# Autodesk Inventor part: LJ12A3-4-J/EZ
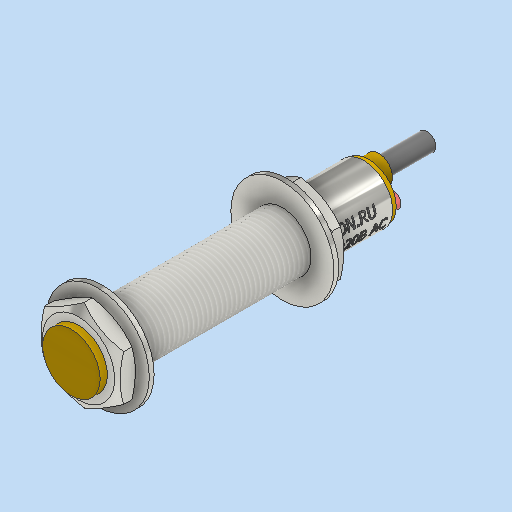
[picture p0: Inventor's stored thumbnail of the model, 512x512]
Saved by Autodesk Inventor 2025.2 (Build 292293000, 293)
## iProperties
Created: 2026-04
Part Number: LJ12A3-4-J/EZ
Material: Типовые
Description: D290-00326
Document SubType Name: Modeling
Designer: DN.RU
Mass: 50 g
Surface Area: 41.1946 cm^2
Volume: 8.64673 cm^3
Density: 5.78253 g/cm^3
Appearance: По умолчанию
Title: Концевой выключатель DN.ru
Author: DN.RU
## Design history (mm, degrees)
sketch "Эскиз1"
  geometry: C1 r 6 at (0, 0); 1 further point
  constraints: 1 centre point, 1 coincident
  dimensions: "d0" = 12 diameter of C1
extrude "Выдавливание1" new body sketch "Эскиз1" distance "d1" = 0.5; taper "d2" = 0 deg
sketch "Эскиз2"
  geometry: C1 r 6 at (0, 0); 1 further point
  constraints: 1 centre point, 1 coincident
  dimensions: "d3" = 12 diameter of C1
extrude "Выдавливание2" join sketch "Эскиз2" distance "d4" = 1; taper "d5" = 0 deg
sketch "Эскиз3"
  geometry: L1 (0, 0)-(8.25, 0); L2 (8.25, -4.763)-(0, -9.526); L3 (0, -9.526)-(-8.25, -4.763); L4 (-8.25, -4.763)-(-8.25, 4.763); L5 (-8.25, 4.763)-(0, 9.526); L6 (0, 9.526)-(8.25, 4.763); L7 (8.25, 4.763)-(8.25, -4.763); 1 further point
  constraints: 14 end point, 1 coincident, 1 horizontal, 1 midpoint, 13 other
  dimensions: "d6" = 8.25 distance of L1.start L1.end
extrude "Выдавливание3" join sketch "Эскиз3" distance "d7" = 4; taper "d8" = 0 deg
sketch "Эскиз4"
  geometry: C1 r 10.75 at (0, 0); 1 further point
  constraints: 1 centre point, 1 coincident
  dimensions: "d9" = 21.5 diameter of C1
extrude "Выдавливание4" join sketch "Эскиз4" distance "d10" = 1; taper "d11" = 0 deg
sketch "Эскиз5"
  geometry: C1 r 6 at (0, 0); 1 further point
  constraints: 1 centre point, 1 coincident
  dimensions: "d12" = 12 diameter of C1
extrude "Выдавливание5" join sketch "Эскиз5" distance "d13" = 37.5; taper "d14" = 0 deg
sketch "Эскиз6"
  geometry: C1 r 10.75 at (0, 0) reference; 1 further point
extrude "Выдавливание6" join sketch "Эскиз6" distance "d15" = 1; taper "d16" = 0 deg
sketch "Эскиз7"
  geometry: L1 (0, 9.526)-(-8.25, 4.763) reference; L2 (8.25, 4.763)-(0, 9.526) reference; L3 (8.25, -4.763)-(8.25, 4.763) reference; L4 (0, -9.526)-(8.25, -4.763) reference; L5 (-8.25, -4.763)-(0, -9.526) reference; L6 (-8.25, 4.763)-(-8.25, -4.763) reference; C1 r 6 at (0, 0) reference; 1 further point
extrude "Выдавливание7" join sketch "Эскиз7" distance "d17" = 4; taper "d18" = 0 deg
sketch "Эскиз9"
  geometry: C1 r 6 at (0, 0); 1 further point
  constraints: 1 centre point, 1 coincident
  dimensions: "d22" = 12 diameter of C1
extrude "Выдавливание9" join sketch "Эскиз9" distance "d23" = 12; taper "d24" = 0 deg
sketch "Эскиз10"
  geometry: C1 r 5.75 at (0, 0); 1 further point
  constraints: 1 centre point, 1 coincident
  dimensions: "d25" = 11.5 diameter of C1
extrude "Выдавливание10" join sketch "Эскиз10" distance "d26" = 1; taper "d27" = 0 deg
sketch "Эскиз11"
  geometry: C1 r 5.75 at (0, 0) reference; C2 r 1.559 at (-4.191, 0); 2 further points
  constraints: 1 centre point, 1 horizontal alignment, 3 other
extrude "Выдавливание11" join sketch "Эскиз11" distance "d29" = 1; taper "d30" = 0 deg
node "Непосредственное редактирование1"
sketch "Эскиз12"
  geometry: C1 r 2.875 at (0, 0) reference; C2 r 1.875 at (0, 0); 1 further point
  constraints: 1 centre point
  dimensions: "d34" = 1 radial gap between concentric circles of C1 C2
extrude "Выдавливание12" join sketch "Эскиз12" distance "d35" = 10; taper "d36" = 0 deg
feature "Резьба1" dims "d37" = 37.5, "d38" = 0
sketch "Эскиз13"
  geometry: L1 (6, 0.5)-(-6, 0.5) reference; L2 (0, 0.5)-(0, 6.956); L3 (9.526, -1)-(9.526, -5) reference; L4 (9.526, -3)-(12.26, -3); L5 (6, -6)-(6, -43.5) reference; L6 (6, -24.75)-(19.06, -24.75); L7 (9.526, -1)-(7.526, -1); L8 (4.763, -1)-(9.526, -1) reference; L9 (7.526, -1)-(9.897, -2.369); L10 (9.897, -2.369)-(9.897, -1); L11 (9.897, -1)-(9.526, -1); L12 (9.526, -5)-(7.526, -5); L13 (7.526, -5)-(9.897, -3.631); L14 (9.897, -3.631)-(9.897, -5); L15 (9.897, -5)-(9.526, -5); L16 (9.526, -48.5)-(7.526, -48.5); L17 (9.897, -48.5)-(9.526, -48.5); L18 (7.526, -48.5)-(9.897, -47.131); L19 (9.897, -47.131)-(9.897, -48.5); L20 (9.526, -48.5)-(9.526, -44.5); L21 (9.526, -44.5)-(7.526, -44.5); L22 (7.526, -44.5)-(9.897, -45.869); L23 (9.897, -45.869)-(9.897, -44.5); L24 (9.897, -44.5)-(9.526, -44.5); 3 further points
  constraints: 40 end point, 13 symmetric about line, 5 point on line, 3 midpoint, 2 horizontal, 2 perpendicular, 1 vertical
  dimensions: "d39" = 2 distance of L3.start L7.end; "d40" = 30 deg angle of L9 L7
revolve "Вращение1" sketch "Эскиз13" stored, may be unused: angle "d41" = 90 deg
node "РабПлоскость1"
sketch "Эскиз14"
  geometry: L1 (2.618, -0.69)-(2.618, -16.362); L2 (2.618, -16.362)-(-5.513, -16.362); L3 (-5.513, -16.362)-(-5.513, -0.69); L4 (-5.513, -0.69)-(2.618, -0.69); 1 further point
  constraints: 2 other
feature "Рельеф1" sketch "Эскиз14" dims "d9" = 21.5, "d42" = 0.1, "d43" = 0
node "Твердое тело1"
node "Спроецированная петля1"
node "Спроецированная петля2"
feature "Перенос1" dims "d33" = 4
other parameters: "d31" = 0, "d32" = 0
